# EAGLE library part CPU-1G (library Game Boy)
First Generation Game Boy CPUs (DMG, MGB, SGB)
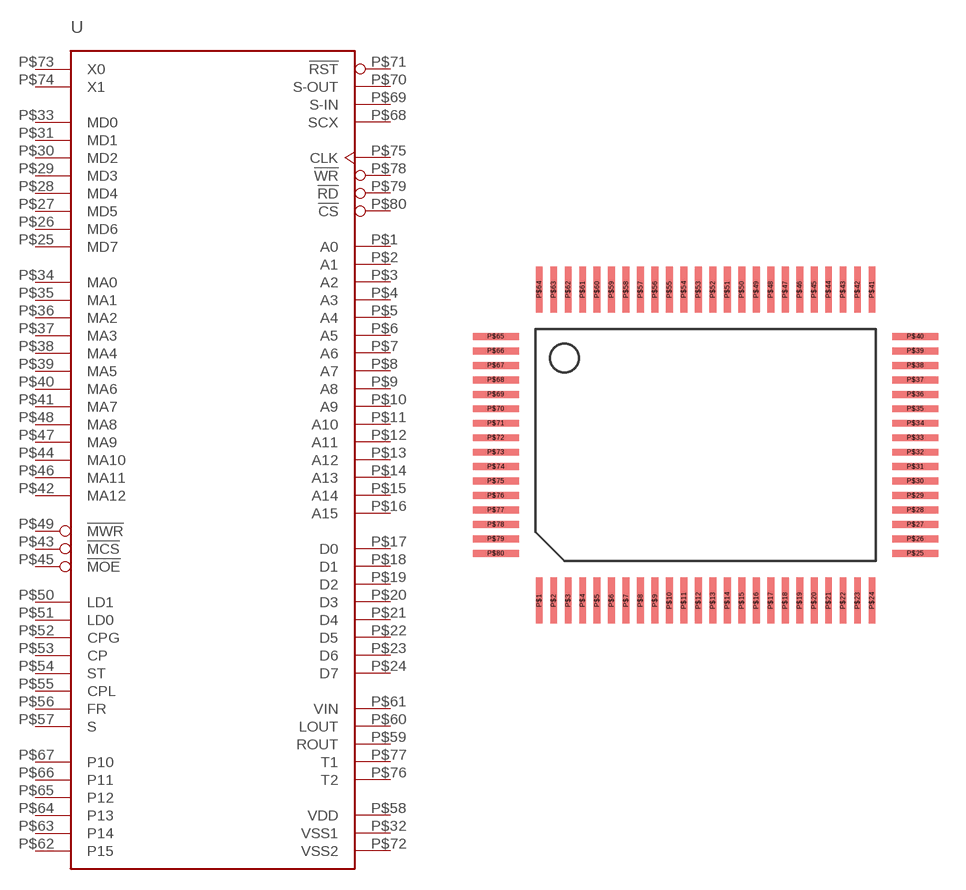
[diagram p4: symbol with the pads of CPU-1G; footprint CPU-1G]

Designator prefix U

## CPU-1GDMG  [CPU-1G]
P$1  A0  out
P$2  A1  out
P$3  A2  out
P$4  A3  out
P$5  A4  out
P$6  A5  out
P$7  A6  out
P$8  A7  out
P$9  A8  out
P$10  A9  out
P$11  A10  out
P$12  A11  out
P$13  A12  out
P$14  A13  out
P$15  A14  out
P$16  A15  out
P$17  D0
P$18  D1
P$19  D2
P$20  D3
P$21  D4
P$22  D5
P$23  D6
P$24  D7
P$25  MD7
P$26  MD6
P$27  MD5
P$28  MD4
P$29  MD3
P$30  MD2
P$31  MD1
P$32  VSS1  pwr
P$33  MD0
P$34  MA0  out
P$35  MA1  out
P$36  MA2  out
P$37  MA3  out
P$38  MA4  out
P$39  MA5  out
P$40  MA6  out
P$41  MA7  out
P$42  MA12  out
P$43  !MCS  out
P$44  MA10  out
P$45  !MOE  out
P$46  MA11  out
P$47  MA9  out
P$48  MA8  out
P$49  !MWR  out
P$50  LD1
P$51  LD0
P$52  CPG
P$53  CP
P$54  ST
P$55  CPL
P$56  FR
P$57  S
P$58  VDD  pwr
P$59  ROUT  out
P$60  LOUT  out
P$61  VIN  in
P$62  P15
P$63  P14
P$64  P13
P$65  P12
P$66  P11
P$67  P10
P$68  SCX
P$69  S-IN  in
P$70  S-OUT  out
P$71  !RST  in
P$72  VSS2  pwr
P$73  X0
P$74  X1
P$75  CLK  out
P$76  T2
P$77  T1
P$78  !WR  out
P$79  !RD  out
P$80  !CS  out

## CPU-1GMGB  [CPU-1G]

## Footprint CPU-1G (pad centres in mm)
smd 0.381 x 2.54: P$1 -9.2,-8.6; P$2 -8.4,-8.6; P$3 -7.6,-8.6; P$4 -6.8,-8.6; P$5 -6,-8.6; P$6 -5.2,-8.6; P$7 -4.4,-8.6; P$8 -3.6,-8.6; P$9 -2.8,-8.6; P$10 -2,-8.6; P$11 -1.2,-8.6; P$12 -0.4,-8.6; P$13 0.4,-8.6; P$14 1.2,-8.6; P$15 2,-8.6; P$16 2.8,-8.6; P$17 3.6,-8.6; P$18 4.4,-8.6; P$19 5.2,-8.6; P$20 6,-8.6; P$21 6.8,-8.6; P$22 7.6,-8.6; P$23 8.4,-8.6; P$24 9.2,-8.6; P$41 9.2,8.6; P$42 8.4,8.6; P$43 7.6,8.6; P$44 6.8,8.6; P$45 6,8.6; P$46 5.2,8.6; P$47 4.4,8.6; P$48 3.6,8.6; P$49 2.8,8.6; P$50 2,8.6; P$51 1.2,8.6; P$52 0.4,8.6; P$53 -0.4,8.6; P$54 -1.2,8.6; P$55 -2,8.6; P$56 -2.8,8.6; P$57 -3.6,8.6; P$58 -4.4,8.6; P$59 -5.2,8.6; P$60 -6,8.6; P$61 -6.8,8.6; P$62 -7.6,8.6; P$63 -8.4,8.6; P$64 -9.2,8.6
smd 2.54 x 0.381: P$25 11.6,-6; P$26 11.6,-5.2; P$27 11.6,-4.4; P$28 11.6,-3.6; P$29 11.6,-2.8; P$30 11.6,-2; P$31 11.6,-1.2; P$32 11.6,-0.4; P$33 11.6,0.4; P$34 11.6,1.2; P$35 11.6,2; P$36 11.6,2.8; P$37 11.6,3.6; P$38 11.6,4.4; P$39 11.6,5.2; P$40 11.6,6; P$65 -11.6,6; P$66 -11.6,5.2; P$67 -11.6,4.4; P$68 -11.6,3.6; P$69 -11.6,2.8; P$70 -11.6,2; P$71 -11.6,1.2; P$72 -11.6,0.4; P$73 -11.6,-0.4; P$74 -11.6,-1.2; P$75 -11.6,-2; P$76 -11.6,-2.8; P$77 -11.6,-3.6; P$78 -11.6,-4.4; P$79 -11.6,-5.2; P$80 -11.6,-6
